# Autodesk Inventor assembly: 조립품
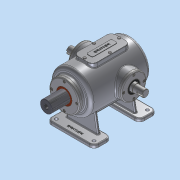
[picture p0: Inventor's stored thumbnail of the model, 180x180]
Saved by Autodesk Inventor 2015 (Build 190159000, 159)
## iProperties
Created: 2016-06
Part Number: 조립품
Document SubType Name: Assembly
Designer: nami
Author: nami
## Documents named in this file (15)
- C:\Users\nami\Desktop\Manufacturing1급\공용부품\답안조립품.iam
- C:\Users\nami\Desktop\Manufacturing1급\공용부품\베어링 6205.ipt
- 베어링 6205.ipt
- C:\Users\nami\Desktop\Manufacturing1급\공용부품\본체.ipt
- C:\Users\nami\Desktop\Manufacturing1급\공용부품\볼트 M4x0.7.ipt
- C:\Users\nami\Desktop\Manufacturing1급\공용부품\부시.ipt
- C:\Users\nami\Desktop\Manufacturing1급\공용부품\상부커버.ipt
- C:\Users\nami\Desktop\Manufacturing1급\공용부품\슬라이드 커버.ipt
- C:\Users\nami\Desktop\Manufacturing1급\공용부품\슬라이드.ipt
- C:\Users\nami\Desktop\Manufacturing1급\공용부품\오일실.ipt
- 오일실.ipt
- C:\Users\nami\Desktop\Manufacturing1급\공용부품\육각머리볼트 M4.ipt
- C:\Users\nami\Desktop\Manufacturing1급\공용부품\축 커버.ipt
- C:\Users\nami\Desktop\Manufacturing1급\공용부품\편심축.ipt
- C:\Users\nami\Desktop\Manufacturing1급\공용부품\가변스프링.ipt
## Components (13 placed, 2 different names)
1. 가변스프링:1
2. M4x0.7:2
3. M4x0.7:3
4. M4x0.7:4
5. M4x0.7:5
6. M4x0.7:1
7. M4x0.7:6
8. M4x0.7:7
9. M4x0.7:8
10. M4x0.7:9
11. M4x0.7:10
12. M4x0.7:11
13. M4x0.7:12
